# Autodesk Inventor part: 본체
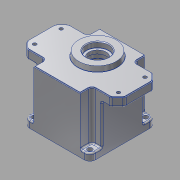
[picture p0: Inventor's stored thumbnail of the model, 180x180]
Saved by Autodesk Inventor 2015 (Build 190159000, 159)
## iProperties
Created: 2016-02
Part Number: 본체
Material: Aluminum 6061
Document SubType Name: Modeling
Designer: Administrator
Density: 2.7 g/cm^3
Appearance: Aluminum - Flat
Mass: 874.397 g
Surface Area: 762.108 cm^2
Volume: 323.851 cm^3
Author: Administrator
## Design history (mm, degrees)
sketch "Sketch1"
  geometry: L1 (-39, -47)-(39, -47); L2 (47, -39)-(47, 39); L3 (39, 47)-(-39, 47); L4 (-47, 39)-(-47, -39); L5 (-47, -47)-(47, 47); L6 (47, -47)-(-47, 47); C1 r 3.5 at (39, 39); C2 r 3.5 at (-39, 39); C3 r 3.5 at (-39, -39); C4 r 3.5 at (39, -39); A1 r 8 centre (-39, 39) between (-39, 47) and (-47, 39); A2 r 8 centre (-39, -39) between (-47, -39) and (-39, -47); A3 r 8 centre (39, -39) between (39, -47) and (47, -39); A4 r 8 centre (39, 39) between (47, 39) and (39, 47); 1 further point
  constraints: 12 end point, 8 centre point, 8 point on circle, 8 point on line, 8 tangent, 6 equal radius, 4 coincident, 2 midpoint, 2 parallel, 2 perpendicular, 1 horizontal
  dimensions: "d0" = 94 distance of L5.end L6.end; "d1" = 8 radius of A1; "d28" = 7 diameter of C1
extrude "Extrusion1" new body sketch "Sketch1" distance "d2" = 10; taper "d3" = 0 deg
sketch "Sketch2"
  geometry: L1 (-33, -47)-(33, -47); L2 (33, -47)-(33, 47); L3 (33, 47)-(-33, 47); L4 (-33, 47)-(-33, -47); L5 (-33, -47)-(33, 47); L6 (33, -47)-(-33, 47); L7 (-60, -30)-(60, -30); L8 (70, -20)-(70, 20); L9 (60, 30)-(-60, 30); L10 (-70, 20)-(-70, -20); L11 (-70, -30)-(70, 30); L12 (70, -30)-(-70, 30); L13 (60, 30)-(70, 20); L14 (70, -20)-(60, -30); L15 (-60, -30)-(-70, -20); L16 (-70, 20)-(-60, 30); 1 further point
  constraints: 32 end point, 8 point on line, 4 midpoint, 4 parallel, 2 horizontal, 2 perpendicular
  dimensions: "d4" = 60 distance of L12.start L11.end; "d5" = 140 distance of L11.end L12.end; "d6" = 66 distance of L2.end L3.end; "d7" = 94 distance of L1.end L2.end; "d8" = 10 distance of L9.start L11.end; "d9" = 10 distance of L8.end L11.end (= d8); "d10" = 10 distance of L8.start L12.start (= d8); "d11" = 10 distance of L7.end L12.start (= d10); "d12" = 10 distance of L7.start L11.start (= d8); "d13" = 10 distance of L10.end L11.start (= d12); "d14" = 10 distance of L10.start L12.end (= d8); "d15" = 10 distance of L9.end L12.end (= d14)
extrude "Extrusion2" join sketch "Sketch2" distance "d16" = 70; taper "d17" = 0 deg
sketch "Sketch4"
  geometry: L1 (60, 30)-(-60, 30) reference; L2 (-70, 20)-(-60, 30) reference; L3 (-70, 20)-(-70, -20) reference; L4 (-60, -30)-(-70, -20) reference; L5 (-60, -30)-(60, -30) reference; L6 (70, -20)-(60, -30) reference; L7 (70, -20)-(70, 20) reference; L8 (60, 30)-(70, 20) reference; 1 further point
extrude "Extrusion5" join sketch "Sketch4" distance "d29" = 13; taper "d30" = 0 deg
sketch "Sketch5"
  geometry: C1 r 28 at (0, 11); 1 further point
  constraints: 1 centre point, 1 vertical alignment
  dimensions: "d31" = 11 distance of point (0, 0) C1.centre; "d32" = 56 diameter of C1
extrude "Extrusion6" join sketch "Sketch5" distance "d33" = 7; taper "d34" = -10 deg
sketch "Sketch8"
  geometry: C1 r 2.5 at (60, 19); C2 r 2.5 at (60, -19); C3 r 2.5 at (-60, -19); C4 r 2.5 at (-60, 19); 1 further point
  constraints: 4 centre point, 3 equal radius, 2 horizontal alignment, 2 vertical alignment
  dimensions: "d39" = 5 diameter of C4; "d40" = 120 distance of C4.centre C1.centre; "d41" = 60 horizontal distance of C4.centre point (0, 0) (= 0.5 x d40); "d42" = 38 distance of C4.centre C3.centre; "d43" = 19 vertical distance of C3.centre point (0, 0)
extrude "Extrusion7" cut sketch "Sketch8" distance "d44" = 9; taper "d45" = 0 deg
sketch "Sketch9"
  geometry: C1 r 2.5 at (-60, -19) reference; C2 r 2.5 at (60, -19) reference; C3 r 2.5 at (60, 19) reference; C4 r 2.5 at (-60, 19) reference; C5 r 4.5 at (-60, 19); C6 r 4.5 at (-60, -19); C7 r 4.5 at (60, 19); C8 r 4.5 at (60, -19); 1 further point
  constraints: 4 centre point, 4 coincident, 3 equal radius
  dimensions: "d46" = 9 diameter of C5
extrude "Extrusion8" cut sketch "Sketch9" distance "d47" = 4; taper "d48" = 0 deg
sketch "Sketch10"
  geometry: C1 r 43 at (0, 0); 1 further point
  constraints: 1 centre point, 1 coincident
  dimensions: "d49" = 86 diameter of C1
extrude "Extrusion9" cut sketch "Sketch10" distance "d50" = 9; taper "d51" = 0 deg
sketch "Sketch12"
  geometry: L1 (-47, -30)-(47, -30); L2 (47, -30)-(47, 30); L3 (47, 30)-(-47, 30); L4 (-47, 30)-(-47, -30); L5 (-47, -30)-(47, 30); L6 (47, -30)-(-47, 30); 1 further point
  constraints: 12 end point, 2 midpoint, 2 parallel, 1 horizontal, 1 perpendicular
  dimensions: "d53" = 94 distance of L2.end L3.end; "d54" = 60 distance of L1.end L2.end
extrude "Extrusion10" join sketch "Sketch12" stored distance "d55" = 62; taper "d56" = 0 deg
sketch "Sketch13"
  geometry: C1 r 40 at (0, 0); 1 further point
  constraints: 1 centre point, 1 coincident
  dimensions: "d57" = 80 diameter of C1
extrude "Extrusion11" cut sketch "Sketch13" distance "d58" = 62; taper "d59" = 0 deg
sketch "Sketch14"
  geometry: C1 r 17.5 at (0, 11); C2 r 11 at (0, -20); A1 r 21 centre (0, 11) between (8.978, -7.984) and (-8.978, -7.984); A2 r 15 centre (0, -20) between (-8.978, -7.984) and (8.978, -7.984); 1 further point
  constraints: 4 centre point, 4 point on circle, 2 coincident, 2 vertical alignment
  dimensions: "d60" = 11 distance of point (0, 0) A1.centre; "d61" = 20 distance of point (0, 0) A2.centre; "d62" = 21 radius of A1; "d63" = 15 radius of A2; "d64" = 35 diameter of C1; "d65" = 22 diameter of C2
extrude "Extrusion12" join sketch "Sketch14" distance "d66" = 7; taper "d67" = 0 deg
hole "Hole1" diameter "d70" = 19; stored, may be unused: countersink angle "d74" = 90 deg, drill point angle "d76" = 0 deg; dims "d68" = 10, "d69" = 10, "d71" = 6, "d72" = 4, "d73" = 2, "d75" = 1
hole "Hole3" diameter "d88" = 25; stored, may be unused: countersink angle "d92" = 90 deg, drill point angle "d94" = 0 deg; dims "d86" = 10, "d87" = 10, "d89" = 6, "d90" = 32, "d91" = 8, "d93" = 13
hole "Hole4" diameter "d97" = 35; stored, may be unused: countersink angle "d101" = 90 deg, drill point angle "d103" = 0 deg; dims "d95" = 10, "d96" = 10, "d98" = 6, "d99" = 32, "d100" = 8, "d102" = 3
sketch "Sketch16"
  geometry: A1 r 36 centre (0, 0) between (-36, 0) and (36, 0); A2 r 4 centre (-36, 0) between (-35.778, -3.994) and (-35.852, 3.997); A3 r 4 centre (36, 0) between (35.852, 3.997) and (35.778, -3.994); A4 r 3.5 centre (-35.722, 7.495) between (-39.148, 8.214) and (-35.778, 3.995); A5 r 4 centre (-35.111, -7.95) between (-35.556, -3.975) and (-39.012, -8.834); A6 r 40 centre (0, 0) between (39.148, 8.214) and (39.012, -8.834) reference; A7 r 3.5 centre (35.722, 7.495) between (35.778, 3.995) and (39.148, 8.214); A8 r 4 centre (35.111, -7.95) between (39.012, -8.834) and (35.556, -3.975); 1 further point
  constraints: 26 point on circle, 8 tangent, 7 centre point, 4 equal radius, 2 horizontal alignment, 1 coincident
  dimensions: "d107" = 36 radius of A1; "d108" = 4 radius of A2; "d109" = 3.5 radius of A4
extrude "Extrusion14" join sketch "Sketch16" stored distance "d110" = 1; taper "d111" = 0 deg
sketch "Sketch17"
  geometry: A1 r 4 centre (-36, 0) between (-35.556, -3.975) and (-35.852, 3.997) reference; A2 r 4 centre (36, 0) between (35.852, 3.997) and (35.556, -3.975) reference; 1 further point
hole "Hole5" sketch "Sketch17" at (36, 0), (-36, 0) diameter "d112" = 3.242; stored, may be unused: countersink angle "d116" = 90 deg, drill point angle "d118" = 118 deg; dims "d113" = 7, "d114" = 32, "d115" = 8, "d117" = 9
fillet "Fillet1" dims "d119" = 0.3
fillet "Fillet2" dims "d120" = 5
chamfer "Chamfer1" distance "d121" = 1; stored, may be unused: second distance "d122" = 2, angle "d123" = 45 deg
fillet "Fillet3" dims "d124" = 2
fillet "Fillet4" dims "d125" = 2
fillet "Fillet5" dims "d126" = 2
sketch "Sketch18" dims "d0" = 94, "d1" = 8, "d28" = 7
  geometry: 2 further points
  constraints: 1 vertical alignment, 1 other
  dimensions: "d127" = 40 distance of point (39, 0) point (39, -40)
emboss "Emboss1" sketch "Sketch18" dims "d0" = 94, "d1" = 8, "d4" = 60, "d5" = 140, "d8" = 10, "d9" = 10 (= d8), "d10" = 10 (= d8), "d11" = 10 (= d10), "d12" = 10 (= d8), "d13" = 10 (= d12), "d14" = 10 (= d8), "d15" = 10 (= d14), "d28" = 7, "d128" = 0.5, "d129" = 0
sketch "Sketch19"
  geometry: L1 (-33, 45)-(-33, 35) reference; L2 (-38, 30)-(-57.929, 30) reference; L3 (-61.464, 28.536)-(-68.536, 21.464) reference; L4 (-70, 17.929)-(-70, -17.929) reference; L5 (-68.536, -21.464)-(-61.464, -28.536) reference; L6 (-57.929, -30)-(-38, -30) reference; L7 (-33, -35)-(-33, -47) reference; L8 (-33, -47)-(33, -47) reference; L9 (33, -47)-(33, -35) reference; L10 (38, -30)-(57.929, -30) reference; L11 (61.464, -28.536)-(68.536, -21.464) reference; L12 (70, -17.929)-(70, 17.929) reference; L13 (68.536, 21.464)-(61.464, 28.536) reference; L14 (57.929, 30)-(38, 30) reference; L15 (33, 35)-(33, 45) reference; L16 (31, 47)-(-31, 47) reference; L17 (-32, 45)-(-32, 35); L18 (-38, 29)-(-57.929, 29); L19 (-60.757, 27.828)-(-67.828, 20.757); L20 (-69, 17.929)-(-69, -17.929); L21 (-67.828, -20.757)-(-60.757, -27.828); L22 (-57.929, -29)-(-38, -29); L23 (-32, -35)-(-32, -46); L24 (-32, -46)-(32, -46); L25 (32, -46)-(32, -35); L26 (38, -29)-(57.929, -29); L27 (60.757, -27.828)-(67.828, -20.757); L28 (69, -17.929)-(69, 17.929); L29 (67.828, 20.757)-(60.757, 27.828); L30 (57.929, 29)-(38, 29); L31 (32, 35)-(32, 45); L32 (31, 46)-(-31, 46); C1 r 28.252 at (0, 11) reference; C2 r 2.5 at (-60, -19) reference; C3 r 2.5 at (-60, 19) reference; C4 r 2.5 at (60, -19) reference; C5 r 2.5 at (60, 19) reference; A1 r 2 centre (-31, 45) between (-31, 47) and (-33, 45) reference; A2 r 5 centre (-38, 35) between (-38, 30) and (-33, 35) reference; A3 r 5 centre (-57.929, 25) between (-57.929, 30) and (-61.464, 28.536) reference; A4 r 5 centre (-65, 17.929) between (-68.536, 21.464) and (-70, 17.929) reference; A5 r 5 centre (-65, -17.929) between (-70, -17.929) and (-68.536, -21.464) reference; A6 r 5 centre (-57.929, -25) between (-61.464, -28.536) and (-57.929, -30) reference; A7 r 5 centre (-38, -35) between (-33, -35) and (-38, -30) reference; A8 r 5 centre (38, -35) between (38, -30) and (33, -35) reference; A9 r 5 centre (57.929, -25) between (57.929, -30) and (61.464, -28.536) reference; A10 r 5 centre (65, -17.929) between (68.536, -21.464) and (70, -17.929) reference; A11 r 5 centre (65, 17.929) between (70, 17.929) and (68.536, 21.464) reference; A12 r 5 centre (57.929, 25) between (61.464, 28.536) and (57.929, 30) reference; A13 r 5 centre (38, 35) between (33, 35) and (38, 30) reference; A14 r 2 centre (31, 45) between (33, 45) and (31, 47) reference; A15 r 1 centre (-31, 45) between (-31, 46) and (-32, 45); A16 r 6 centre (-38, 35) between (-38, 29) and (-32, 35); A17 r 4 centre (-57.929, 25) between (-57.929, 29) and (-60.757, 27.828); A18 r 4 centre (-65, 17.929) between (-67.828, 20.757) and (-69, 17.929); A19 r 4 centre (-65, -17.929) between (-69, -17.929) and (-67.828, -20.757); A20 r 4 centre (-57.929, -25) between (-60.757, -27.828) and (-57.929, -29); A21 r 6 centre (-38, -35) between (-32, -35) and (-38, -29); A22 r 6 centre (38, -35) between (38, -29) and (32, -35); A23 r 4 centre (57.929, -25) between (57.929, -29) and (60.757, -27.828); A24 r 4 centre (65, -17.929) between (67.828, -20.757) and (69, -17.929); A25 r 4 centre (65, 17.929) between (69, 17.929) and (67.828, 20.757); A26 r 4 centre (57.929, 25) between (60.757, 27.828) and (57.929, 29); A27 r 6 centre (38, 35) between (32, 35) and (38, 29); A28 r 1 centre (31, 45) between (32, 45) and (31, 46); 1 further point
  constraints: 32 end point, 28 point on circle, 14 centre point, 29 other
  dimensions: "d130" = 1 distance between parallel lines of L16 L32
extrude "Extrusion15" cut sketch "Sketch19" distance "d131" = 1; taper "d132" = 0 deg
fillet "Fillet6" dims "d133" = 2
fillet "Fillet7" dims "d134" = 2
sketch "Sketch20"
  geometry: C1 r 3.5 at (40, 40); C2 r 3.5 at (-40, 40); C3 r 3.5 at (-40, -40); C4 r 3.5 at (40, -40); 1 further point
  constraints: 4 centre point, 3 equal radius, 2 horizontal alignment, 2 vertical alignment
  dimensions: "d135" = 7 diameter of C1; "d136" = 80 distance of C4.centre C3.centre; "d137" = 40 horizontal distance of point (0, 0) C4.centre (= 0.5 x d136); "d138" = 80 distance of C1.centre C4.centre; "d139" = 40 horizontal distance of point (0, 0) C1.centre (= 0.5 x d138)
extrude "Extrusion16" cut sketch "Sketch20" stored distance "d140" = 1; taper "d141" = 0 deg
body "Solid1"
node "Projected Loop1"
